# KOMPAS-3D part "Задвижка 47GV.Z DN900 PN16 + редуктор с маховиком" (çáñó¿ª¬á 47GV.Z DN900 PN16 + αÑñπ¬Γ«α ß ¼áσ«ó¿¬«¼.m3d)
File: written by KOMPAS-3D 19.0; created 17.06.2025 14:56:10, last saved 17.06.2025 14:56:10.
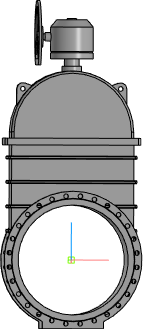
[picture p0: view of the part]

Document properties: Полное имя файла: Задвижка 47GV.Z DN900 PN16 + редуктор с маховиком.a3d

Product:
- Part/product: Задвижка 47GV.Z DN900 PN16 + редуктор с маховиком
    Масса: 3574.09

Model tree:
1. Операция без истории:1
